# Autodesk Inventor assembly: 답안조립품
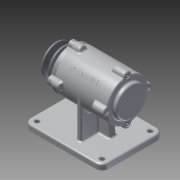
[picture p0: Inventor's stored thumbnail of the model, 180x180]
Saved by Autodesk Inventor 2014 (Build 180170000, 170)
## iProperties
Created: 2015-12
Part Number: 답안조립품
Document SubType Name: Assembly
Designer: test_03
Author: test_03
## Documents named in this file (11)
- C:\Users\test_03\Desktop\451207V1024\답안조립품.iam
- C:\Users\test_03\Desktop\451207V1024\V-벨트풀리.ipt
- C:\Users\test_03\Desktop\451207V1024\너트 M12x1.25.ipt
- C:\Users\test_03\Desktop\451207V1024\베어링 6204.ipt
- C:\Users\test_03\Desktop\451207V1024\본체.ipt
- C:\Users\test_03\Desktop\451207V1024\볼트 M4 x 12.ipt
- C:\Users\test_03\Desktop\451207V1024\오일실.ipt
- C:\Users\test_03\Desktop\451207V1024\축.ipt
- C:\Users\test_03\Desktop\451207V1024\커버.ipt
- C:\Users\test_03\Desktop\451207V1024\커버2.ipt
- C:\Users\test_03\Desktop\451207V1024\키(4 x 4 x 12).ipt
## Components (6 placed, 5 different names)
1. V-벨트풀리:1
2. KS B 1012 클래스 1 일반 - 미터 M12x1.25:1
3. KS B 2023 6204 - 20 x 47 x 14:1
4. KS B 2804 D D - 20 32 8:1
5. KS B 1311 (I) 4 x 4 x 12:1
6. KS B 2023 6204 - 20 x 47 x 14:2
